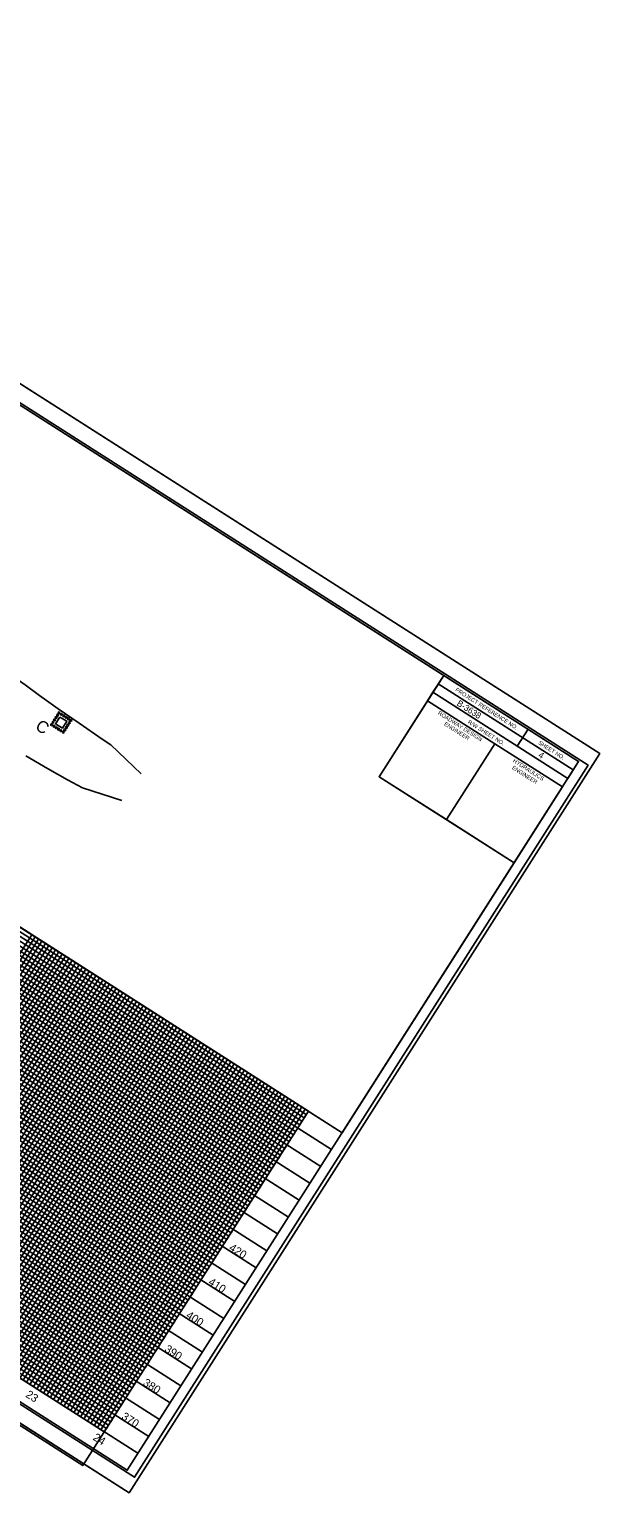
# Model space of a CAD drawing. Extents: x 2023536 to 2025544, y 819438 to 821266.
# Drawn here: x 2024831 to 2025544, y 819438 to 821266 of the extents above; entities that cross this region are included whole.
import ezdxf

# ---------------------------------------------------------------- set-up
doc = ezdxf.new("R2010")
doc.units = 0
for name, color, linetype in [('Exist Vertical Profile Horizontal Axis Label Major', 7, 'Continuous'), ('Exist Vertical Profile Vertical Axis Label', 7, 'Continuous'), ('Label C Final CELL', 7, 'Continuous'), ('Rock Inlet Sediment Trap Type C Final CELL', 7, 'Continuous'), ('Sheet Clip Boundary CELL', 7, 'Continuous'), ('Sheet Cutting Line CELL', 7, 'Continuous'), ('Sheet Data Field CELL', 7, 'Continuous'), ('Sheet DOT Grid CELL', 7, 'Continuous'), ('Sheet Layout Profile Border Port 2', 7, 'Continuous'), ('Sheet Plan And Profile CELL', 7, 'Continuous'), ('Sheet Plot Border Inside CELL', 7, 'Continuous'), ('Sheet Plot Border Outside CELL', 7, 'Continuous'), ('Sheet Profile Grid Major CELL', 7, 'Continuous'), ('Sheet Profile Grid Middle CELL', 7, 'Continuous'), ('Sheet Profile Grid Minor CELL', 7, 'Continuous'), ('Temporary Silt Fence Both', 7, 'Continuous')]:
    doc.layers.add(name, color=color, linetype=linetype)

msp = doc.modelspace()

# ---------------------------------------------------------------- linework, layer by layer
at = {"layer": 'Rock Inlet Sediment Trap Type C Final CELL'}
msp.add_lwpolyline([(2024869.5, 820407.1), (2024877.9, 820401.8), (2024872.5, 820393.3), (2024864.1, 820398.7)], close=True, dxfattribs=at)
for centre in [(2024868.3, 820412.3), (2024871.3, 820410.5), (2024858.9, 820397.6), (2024860.8, 820400.5), (2024861.9, 820395.7), (2024862.7, 820403.5), (2024864.6, 820406.4), (2024864.8, 820393.8), (2024866.5, 820409.4), (2024867.8, 820391.9), (2024874.3, 820408.6), (2024875.6, 820391.1), (2024877.2, 820406.7), (2024877.5, 820394.1), (2024879.3, 820397), (2024880.2, 820404.8), (2024881.2, 820400), (2024883.1, 820402.9), (2024870.7, 820390.1), (2024873.7, 820388.2)]:
    msp.add_circle(centre, 1.12, dxfattribs=at)
at = {"layer": 'Sheet Clip Boundary CELL'}
for points in [[(2023957.3, 820694), (2024252.9, 821157.8), (2024518.4, 820988.6), (2024450.6, 820880.9), (2024650, 820753), (2024719.3, 820860.6), (2025349.2, 820459.2), (2025268.5, 820332.6), (2025437.2, 820225.1), (2025222.2, 819887.8)], [(2023972.6, 820625), (2025153.2, 819872.5), (2024897.9, 819472), (2023717.3, 820224.4)]]:
    msp.add_lwpolyline(points, close=True, dxfattribs=at)
at = {"layer": 'Sheet Cutting Line CELL'}
for p, q in [((2025544.3, 820361.5), (2024124.6, 821266.3)), ((2023536.1, 820342.9), (2024955.8, 819438.1))]:
    msp.add_line(p, q, dxfattribs=at)
at = {"layer": 'Sheet DOT Grid CELL'}
for p, q in [((2023930.4, 820651.9), (2025195.4, 819845.7)), ((2023903.6, 820609.7), (2025168.5, 819803.5)), ((2023876.7, 820567.5), (2025141.6, 819761.3)), ((2023849.8, 820525.4), (2025114.8, 819719.2)), ((2023822.9, 820483.2), (2025087.9, 819677)), ((2023796.1, 820441), (2025061, 819634.8)), ((2023769.2, 820398.9), (2025034.1, 819592.7)), ((2023742.3, 820356.7), (2025007.3, 819550.5)), ((2023715.5, 820314.5), (2024980.4, 819508.4)), ((2024716.3, 820210.3), (2025222.2, 819887.8)), ((2024842.8, 820129.7), (2024587.5, 819729.1)), ((2024884.9, 820102.8), (2024629.6, 819702.3)), ((2024927.1, 820075.9), (2024671.8, 819675.4)), ((2024969.3, 820049.1), (2024714, 819648.5)), ((2025011.4, 820022.2), (2024756.1, 819621.6)), ((2025053.6, 819995.3), (2024798.3, 819594.8)), ((2025095.8, 819968.5), (2024840.5, 819567.9)), ((2025137.9, 819941.6), (2024882.6, 819541)), ((2025180.1, 819914.7), (2024924.8, 819514.1))]:
    msp.add_line(p, q, dxfattribs=at)
at = {"layer": 'Sheet Layout Profile Border Port 2'}
msp.add_lwpolyline([(2024716.3, 820210.3), (2025180.1, 819914.7), (2024924.8, 819514.1), (2023744.2, 820266.6), (2023999.5, 820667.1), (2024041.6, 820640.3)], dxfattribs=at)
at = {"layer": 'Sheet Plan And Profile CELL'}
for p, q in [((2025342.4, 820448.6), (2025511.1, 820341.1)), ((2025335.7, 820438), (2025329, 820427.5)), ((2025335.7, 820438), (2025504.4, 820330.5)), ((2025454.6, 820391.9), (2025441.1, 820370.8)), ((2025413.3, 820373.7), (2025352.9, 820278.9)), ((2024967, 819487.3), (2023702, 820293.5))]:
    msp.add_line(p, q, dxfattribs=at)
for points in [[(2025517.9, 820351.6), (2024252.9, 821157.8), (2023688.6, 820272.4), (2024953.5, 819466.2)], [(2025349.2, 820459.2), (2025517.9, 820351.6), (2025504.4, 820330.5), (2025335.7, 820438)], [(2025329, 820427.5), (2025413.3, 820373.7), (2025352.9, 820278.9), (2025268.5, 820332.6)], [(2025413.3, 820373.7), (2025497.7, 820320), (2025437.2, 820225.1), (2025352.9, 820278.9)]]:
    msp.add_lwpolyline(points, close=True, dxfattribs=at)
at = {"layer": 'Sheet Plot Border Inside CELL'}
msp.add_lwpolyline([(2023557.8, 820352.8), (2024962.7, 819457.4), (2025529.7, 820347), (2024124.8, 821242.4)], close=True, dxfattribs=at)
at = {"layer": 'Sheet Plot Border Outside CELL'}
msp.add_lwpolyline([(2023536.1, 820342.9), (2024955.8, 819438.1), (2025544.3, 820361.5), (2024124.6, 821266.3)], close=True, dxfattribs=at)
at = {"layer": 'Sheet Profile Grid Major CELL'}
for points in [[(2025195.4, 819845.7), (2023930.4, 820651.9), (2023903.6, 820609.7), (2025168.5, 819803.5)], [(2025141.6, 819761.3), (2023876.7, 820567.5), (2023849.8, 820525.4), (2025114.8, 819719.2)], [(2025087.9, 819677), (2023822.9, 820483.2), (2023796.1, 820441), (2025061, 819634.8)], [(2025034.1, 819592.7), (2023769.2, 820398.9), (2023742.3, 820356.7), (2025007.3, 819550.5)], [(2024980.4, 819508.4), (2023715.5, 820314.5)], [(2024716.3, 820210.3), (2025222.2, 819887.8)], [(2024587.5, 819729.1), (2024842.8, 820129.7), (2024884.9, 820102.8), (2024629.6, 819702.3)], [(2024671.8, 819675.4), (2024927.1, 820075.9), (2024969.3, 820049.1), (2024714, 819648.5)], [(2024756.1, 819621.6), (2025011.4, 820022.2), (2025053.6, 819995.3), (2024798.3, 819594.8)], [(2024840.5, 819567.9), (2025095.8, 819968.5), (2025137.9, 819941.6), (2024882.6, 819541)], [(2024924.8, 819514.1), (2025180.1, 819914.7)]]:
    msp.add_lwpolyline(points, dxfattribs=at)
at = {"layer": 'Sheet Profile Grid Middle CELL'}
for p, q in [((2025181.9, 819824.6), (2023917, 820630.8)), ((2023890.1, 820588.6), (2025155.1, 819782.4)), ((2025128.2, 819740.3), (2023863.3, 820546.4)), ((2023836.4, 820504.3), (2025101.3, 819698.1)), ((2025074.4, 819655.9), (2023809.5, 820462.1)), ((2023782.6, 820420), (2025047.6, 819613.8)), ((2025020.7, 819571.6), (2023755.8, 820377.8)), ((2023728.9, 820335.6), (2024993.8, 819529.4)), ((2024702.8, 820189.2), (2025208.8, 819866.8))]:
    msp.add_line(p, q, dxfattribs=at)
for points in [[(2024608.6, 819715.7), (2024863.9, 820116.3), (2024906, 820089.4), (2024650.7, 819688.8)], [(2024692.9, 819661.9), (2024948.2, 820062.5), (2024990.3, 820035.6), (2024735.1, 819635.1)], [(2024777.2, 819608.2), (2025032.5, 820008.8), (2025074.7, 819981.9), (2024819.4, 819581.3)], [(2024861.5, 819554.5), (2025116.8, 819955), (2025159, 819928.1), (2024903.7, 819527.6)]]:
    msp.add_lwpolyline(points, dxfattribs=at)
at = {"layer": 'Sheet Profile Grid Minor CELL'}
for points in [[(2023943, 820578.6), (2023945.7, 820582.8), (2023948.4, 820587), (2025129, 819834.6), (2025131.7, 819838.8), (2023951.1, 820591.3), (2023953.8, 820595.5), (2025134.4, 819843), (2025137.1, 819847.2), (2023956.5, 820599.7), (2023959.2, 820603.9), (2023961.9, 820608.1), (2025142.5, 819855.7), (2025145.2, 819859.9), (2023964.5, 820612.3), (2023967.2, 820616.6), (2025147.8, 819864.1), (2025150.5, 819868.3), (2023969.9, 820620.8), (2023972.6, 820625), (2023975.3, 820629.2), (2024017.5, 820602.3)], [(2023943, 820578.6), (2025123.7, 819826.2)], [(2023929.6, 820557.5), (2025110.2, 819805.1), (2025115.6, 819813.5), (2023935, 820566)], [(2023937.7, 820570.2), (2025118.3, 819817.7), (2025121, 819821.9), (2023940.4, 820574.4)], [(2023916.2, 820536.4), (2025096.8, 819784), (2025102.2, 819792.4), (2023921.5, 820544.9)], [(2023924.2, 820549.1), (2025104.8, 819796.6), (2025107.5, 819800.9), (2023926.9, 820553.3)], [(2023902.7, 820515.4), (2025083.3, 819762.9), (2025088.7, 819771.3), (2023908.1, 820523.8)], [(2023910.8, 820528), (2025091.4, 819775.6), (2025094.1, 819779.8), (2023913.5, 820532.2)], [(2023889.3, 820494.3), (2025069.9, 819741.8), (2025075.3, 819750.3), (2023894.7, 820502.7)], [(2023897.4, 820506.9), (2025078, 819754.5), (2025080.7, 819758.7), (2023900, 820511.1)], [(2023883.9, 820485.8), (2025064.5, 819733.4), (2025067.2, 819737.6), (2023886.6, 820490.1)], [(2023870.5, 820464.8), (2025051.1, 819712.3), (2025053.8, 819716.5), (2023873.2, 820469)], [(2023875.9, 820473.2), (2025056.5, 819720.8), (2025061.8, 819729.2), (2023881.2, 820481.6)], [(2023857.1, 820443.7), (2025037.7, 819691.2), (2025040.3, 819695.5), (2023859.7, 820447.9)], [(2023862.4, 820452.1), (2025043, 819699.7), (2025048.4, 819708.1), (2023867.8, 820460.5)], [(2023849, 820431), (2025029.6, 819678.6), (2025035, 819687), (2023854.4, 820439.5)], [(2023835.6, 820409.9), (2025016.2, 819657.5), (2025021.5, 819665.9), (2023840.9, 820418.4)], [(2023843.6, 820422.6), (2025024.2, 819670.2), (2025026.9, 819674.4), (2023846.3, 820426.8)], [(2023822.1, 820388.9), (2025002.7, 819636.4), (2025008.1, 819644.9), (2023827.5, 820397.3)], [(2023830.2, 820401.5), (2025010.8, 819649.1), (2025013.5, 819653.3), (2023832.9, 820405.7)], [(2023808.7, 820367.8), (2024989.3, 819615.3), (2024994.7, 819623.8), (2023814.1, 820376.2)], [(2023816.7, 820380.4), (2024997.3, 819628), (2025000, 819632.2), (2023819.4, 820384.6)], [(2023803.3, 820359.3), (2024983.9, 819606.9), (2024986.6, 819611.1), (2023806, 820363.6)], [(2023789.9, 820338.3), (2024970.5, 819585.8), (2024973.2, 819590), (2023792.6, 820342.5)], [(2023795.2, 820346.7), (2024975.9, 819594.3), (2024981.2, 819602.7), (2023800.6, 820355.1)], [(2023746.9, 820270.8), (2024927.5, 819518.4), (2024930.2, 819522.6), (2023749.6, 820275), (2023752.2, 820279.2), (2024932.9, 819526.8), (2024935.5, 819531), (2023754.9, 820283.5), (2023757.6, 820287.7), (2023760.3, 820291.9), (2024940.9, 819539.4), (2024943.6, 819543.7), (2023763, 820296.1), (2023765.7, 820300.3), (2024946.3, 819547.9), (2024949, 819552.1), (2023768.4, 820304.5), (2023771.1, 820308.7), (2023773.7, 820313), (2024954.4, 819560.5), (2024957, 819564.7), (2023776.4, 820317.2), (2023779.1, 820321.4), (2024959.7, 819569)], [(2023781.8, 820325.6), (2024962.4, 819573.2), (2024967.8, 819581.6), (2023787.2, 820334)], [(2024705.5, 820193.4), (2025169.3, 819897.8), (2025172, 819902.1), (2024708.2, 820197.7)], [(2024710.9, 820201.9), (2025174.7, 819906.3), (2025177.4, 819910.5), (2024713.6, 820206.1)], [(2024692.1, 820172.4), (2025155.9, 819876.8), (2025158.6, 819881), (2024694.8, 820176.6)], [(2024697.5, 820180.8), (2025161.3, 819885.2), (2025164, 819889.4), (2024700.2, 820185)], [(2024579, 819734.5), (2024834.3, 820135.1), (2024838.6, 820132.4), (2024583.3, 819731.8)], [(2024591.7, 819726.4), (2024847, 820127), (2024851.2, 820124.3), (2024595.9, 819723.8)], [(2024600.1, 819721.1), (2024855.4, 820121.6), (2024859.6, 820118.9), (2024604.3, 819718.4)], [(2024612.8, 819713), (2024868.1, 820113.6), (2024872.3, 820110.9), (2024617, 819710.3)], [(2024621.2, 819707.6), (2024876.5, 820108.2), (2024880.7, 820105.5), (2024625.4, 819704.9)], [(2024633.9, 819699.6), (2024889.1, 820100.1), (2024893.4, 820097.4), (2024638.1, 819696.9)], [(2024642.3, 819694.2), (2024897.6, 820094.8), (2024901.8, 820092.1), (2024646.5, 819691.5)], [(2024654.9, 819686.1), (2024910.2, 820086.7), (2024914.4, 820084), (2024659.2, 819683.4)], [(2024663.4, 819680.8), (2024918.7, 820081.3), (2024922.9, 820078.6), (2024667.6, 819678.1)], [(2024676, 819672.7), (2024931.3, 820073.3), (2024935.5, 820070.6), (2024680.2, 819670)], [(2024684.5, 819667.3), (2024939.7, 820067.9), (2024944, 820065.2), (2024688.7, 819664.6)], [(2024697.1, 819659.3), (2024952.4, 820059.8), (2024956.6, 820057.1), (2024701.3, 819656.6)], [(2024705.5, 819653.9), (2024960.8, 820054.4), (2024965, 820051.8), (2024709.8, 819651.2)], [(2024718.2, 819645.8), (2024973.5, 820046.4), (2024977.7, 820043.7), (2024722.4, 819643.1)], [(2024726.6, 819640.4), (2024981.9, 820041), (2024986.1, 820038.3), (2024730.8, 819637.8)], [(2024739.3, 819632.4), (2024994.6, 820032.9), (2024998.8, 820030.3), (2024743.5, 819629.7)], [(2024747.7, 819627), (2025003, 820027.6), (2025007.2, 820024.9), (2024751.9, 819624.3)], [(2024760.4, 819618.9), (2025015.6, 820019.5), (2025019.9, 820016.8), (2024764.6, 819616.3)], [(2024768.8, 819613.6), (2025024.1, 820014.1), (2025028.3, 820011.4), (2024773, 819610.9)], [(2024781.4, 819605.5), (2025036.7, 820006.1), (2025040.9, 820003.4), (2024785.6, 819602.8)], [(2024789.9, 819600.1), (2025045.2, 820000.7), (2025049.4, 819998), (2024794.1, 819597.5)], [(2024802.5, 819592.1), (2025057.8, 819992.6), (2025062, 819990), (2024806.7, 819589.4)], [(2024810.9, 819586.7), (2025066.2, 819987.3), (2025070.5, 819984.6), (2024815.2, 819584)], [(2024823.6, 819578.6), (2025078.9, 819979.2), (2025083.1, 819976.5), (2024827.8, 819576)], [(2024832, 819573.3), (2025087.3, 819973.8), (2025091.5, 819971.1), (2024836.2, 819570.6)], [(2024844.7, 819565.2), (2025100, 819965.8), (2025104.2, 819963.1), (2024848.9, 819562.5)], [(2024853.1, 819559.8), (2025108.4, 819960.4), (2025112.6, 819957.7), (2024857.3, 819557.1)], [(2024865.8, 819551.8), (2025121.1, 819952.3), (2025125.3, 819949.6), (2024870, 819549.1)], [(2024874.2, 819546.4), (2025129.5, 819947), (2025133.7, 819944.3), (2024878.4, 819543.7)], [(2024886.8, 819538.3), (2025142.1, 819938.9), (2025146.4, 819936.2), (2024891.1, 819535.6)], [(2024895.3, 819533), (2025150.6, 819933.5), (2025154.8, 819930.8), (2024899.5, 819530.3)], [(2024907.9, 819524.9), (2025163.2, 819925.5), (2025167.4, 819922.8), (2024912.1, 819522.2)], [(2024916.4, 819519.5), (2025171.7, 819920.1), (2025175.9, 819917.4), (2024920.6, 819516.8)]]:
    msp.add_lwpolyline(points, dxfattribs=at)
at = {"layer": 'Temporary Silt Fence Both'}
for points in [[(2024804.1, 820462.4), (2024825.9, 820447.5), (2024844, 820434.2), (2024867.4, 820417.3), (2024893.5, 820399.5), (2024922.2, 820379.6), (2024933.1, 820372.4), (2024970.8, 820336.3)], [(2024826.8, 820358.6), (2024854, 820342.7), (2024878.7, 820328.8), (2024897.8, 820318.6), (2024946.7, 820302.7)]]:
    msp.add_lwpolyline(points, dxfattribs=at)

# ---------------------------------------------------------------- texts
at = {"layer": 'Exist Vertical Profile Horizontal Axis Label Major'}
for s, p in [('23', (2024825.7, 819558.4)), ('24', (2024909.9, 819504.8))]:
    msp.add_text(s, height=10, rotation=327.4893, dxfattribs=at).set_placement(p)
at = {"layer": 'Exist Vertical Profile Vertical Axis Label'}
for s, p in [('420', (2025079.9, 819741.7)), ('410', (2025054, 819698.9)), ('400', (2025026.2, 819657.4)), ('390', (2024999.3, 819615.2)), ('380', (2024972.4, 819573)), ('370', (2024945.5, 819530.9))]:
    msp.add_text(s, height=10, rotation=327.4893, dxfattribs=at).set_placement(p)
at = {"layer": 'Label C Final CELL'}
msp.add_text('C', height=15, rotation=327.4893, dxfattribs=at).set_placement((2024837.5, 820392.4))
at = {"layer": 'Sheet Data Field CELL'}
for s, p in [('B-3638   ', (2025364.8, 820422.3)), ('4  ', (2025466.7, 820357.7))]:
    msp.add_text(s, height=7.75, rotation=327.4893, dxfattribs=at).set_placement(p)
at = {"layer": 'Sheet Plan And Profile CELL'}
for s, p in [('PROJECT REFERENCE NO.', (2025363.2, 820439.9)), ('ROADWAY DESIGN', (2025341.4, 820410.9)), ('ENGINEER', (2025349.1, 820397.1)), ('R/W SHEET NO.', (2025378.8, 820399.6)), ('SHEET NO.', (2025467, 820373.6)), ('ENGINEER', (2025434, 820342.5)), ('HYDRAULICS', (2025435.1, 820351.2))]:
    msp.add_text(s, height=5, rotation=327.4893, dxfattribs=at).set_placement(p)

doc.saveas('drawing.dxf')
